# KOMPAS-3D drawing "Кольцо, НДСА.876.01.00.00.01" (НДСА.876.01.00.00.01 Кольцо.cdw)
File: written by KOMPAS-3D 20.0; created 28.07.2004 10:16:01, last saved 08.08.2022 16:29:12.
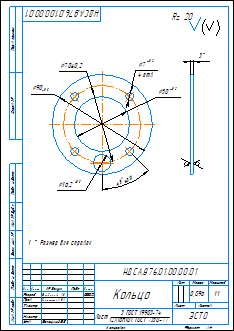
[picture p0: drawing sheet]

Sheet 1: A4, portrait

Document properties: Полное имя файла: C:\Users\cherbakova\Desktop\Барсук\НДСА.876.00.00.00.00 Нагреватель горизонтальный\НДСА.876.01.00.00.01 Кольцо.cdw; Масса: 0.0957047; Знак неуказанной шероховатости: 4; Параметр неуказанной шероховатости: Rz 20; 310031503008: <item xmlns="http://appius.ru/pdm" xmlns:xs="http://www.w3.org/2001/XMLSchema" xmlns:xsi="http://www.w3.org/2001/XMLSchema-instance" xsi:type="item">  <element xmlns:d2p1="http://v8.1c.ru/8.1/data/enterprise/current-config" xsi:type="d2p1:CatalogRef.aps_Элемен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; 310031503108: <item xmlns="http://appius.ru/pdm" xmlns:xs="http://www.w3.org/2001/XMLSchema" xmlns:xsi="http://www.w3.org/2001/XMLSchema-instance" xsi:type="item">  <element xmlns:d2p1="http://v8.1c.ru/8.1/data/enterprise/current-config" xsi:type="d2p1:CatalogRef.aps_Элемен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; 254322297374: <item xmlns="http://appius.ru/pdm" xmlns:xs="http://www.w3.org/2001/XMLSchema" xmlns:xsi="http://www.w3.org/2001/XMLSchema-instance" xsi:type="item">  <element xmlns:d2p1="http://v8.1c.ru/8.1/data/enterprise/current-config" xsi:type="d2p1:CatalogRef.aps_Элемен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; 254322297474: <item xmlns="http://appius.ru/pdm" xmlns:xs="http://www.w3.org/2001/XMLSchema" xmlns:xsi="http://www.w3.org/2001/XMLSchema-instance" xsi:type="item">  <element xmlns:d2p1="http://v8.1c.ru/8.1/data/enterprise/current-config" xsi:type="d2p1:CatalogRef.aps_Элемен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; 232651273862: <item xmlns="http://appius.ru/pdm" xmlns:xs="http://www.w3.org/2001/XMLSchema" xmlns:xsi="http://www.w3.org/2001/XMLSchema-instance" xsi:type="item">  <element xmlns:d2p1="http://v8.1c.ru/8.1/data/enterprise/current-config" xsi:type="d2p1:CatalogRef.aps_Элемен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; 232651273962: <item xmlns="http://appius.ru/pdm" xmlns:xs="http://www.w3.org/2001/XMLSchema" xmlns:xsi="http://www.w3.org/2001/XMLSchema-instance" xsi:type="item">  <element xmlns:d2p1="http://v8.1c.ru/8.1/data/enterprise/current-config" xsi:type="d2p1:CatalogRef.aps_Элемен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; 364072649307: <item xmlns="http://appius.ru/pdm" xmlns:xs="http://www.w3.org/2001/XMLSchema" xmlns:xsi="http://www.w3.org/2001/XMLSchema-instance" xsi:type="item">  <element xmlns:d2p1="http://v8.1c.ru/8.1/data/enterprise/current-config" xsi:type="d2p1:CatalogRef.aps_Элемен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; Количество листов документа: 1; PLM_CDWXDTO: <item xmlns="http://appius.ru/pdm" xmlns:xs="http://www.w3.org/2001/XMLSchema" xmlns:xsi="http://www.w3.org/2001/XMLSchema-instance" xsi:type="item">  <element xmlns:d2p1="http://v8.1c.ru/8.1/data/enterprise/current-config" xsi:type="d2p1:CatalogRef.aps_Элемен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

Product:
- Part/product: Кольцо  | designation НДСА.876.01.00.00.01
    Материал: Лист $b3 ГОСТ 19903-74;12Х18Н10Т ГОСТ 7350-77$ (density 7900 kg/m3)
    Масса: 0.0957047
    Раздел спецификации: Детали
    additional columns: <item xmlns="http://appius.ru/pdm" xmlns:xs="http://www.w3.org/2001/XMLSchema" x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; <item xmlns="http://appius.ru/pdm" xmlns:xs="http://www.w3.org/2001/XMLSchema" x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; <item xmlns="http://appius.ru/pdm" xmlns:xs="http://www.w3.org/2001/XMLSchema" x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; <item xmlns="http://appius.ru/pdm" xmlns:xs="http://www.w3.org/2001/XMLSchema" x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; <item xmlns="http://appius.ru/pdm" xmlns:xs="http://www.w3.org/2001/XMLSchema" x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; <item xmlns="http://appius.ru/pdm" xmlns:xs="http://www.w3.org/2001/XMLSchema" x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

Title block, sheet 1: Наименование: Кольцо; designation: НДСА.876.01.00.00.01; Материал: Лист  3 ГОСТ 19903-74 12Х18Н10Т ГОСТ 7350-77; Масса: 0,096; scale: 1:1; organisation: ЭСТО; Форматы листов документа: A4; stored path: \\Cmp21\Work Kompas\Термо-рабочий проект\737.00.00.00.00 Установка Каролина D12A\БПКЖ.737.03.00.00.00 Нагреватель\БПКЖ.737.03.02.00.00 Кронштейн\БПКЖ.737.03.02.00.01 Кольцо.cdw; Разработал: Щербакова А.В.; Проверил: Горностаев. П.А.; Утвердил: Белецкий В.Е.; Разработал, date: 03.08.2022

Views: Вид 1, Сверху, Проекционный вид 2
Referenced files in C:\Users\cherbakova\Desktop\Барсук\НДСА.876.00.00.00.00 Нагреватель горизонтальный\: НДСА.876.01.00.00.01 Кольцо.m3d
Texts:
  СК 1
  Rz 20
  НДСА.876.01.00.00.01 Кольцо
Dimensions and other numbers on the sheet: 50; 90; 7; 4 отв.; 16,2; 70±0,2; 3; 1:1; 0,096; 03.08.2022; 1

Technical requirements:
  * Размер для справок.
